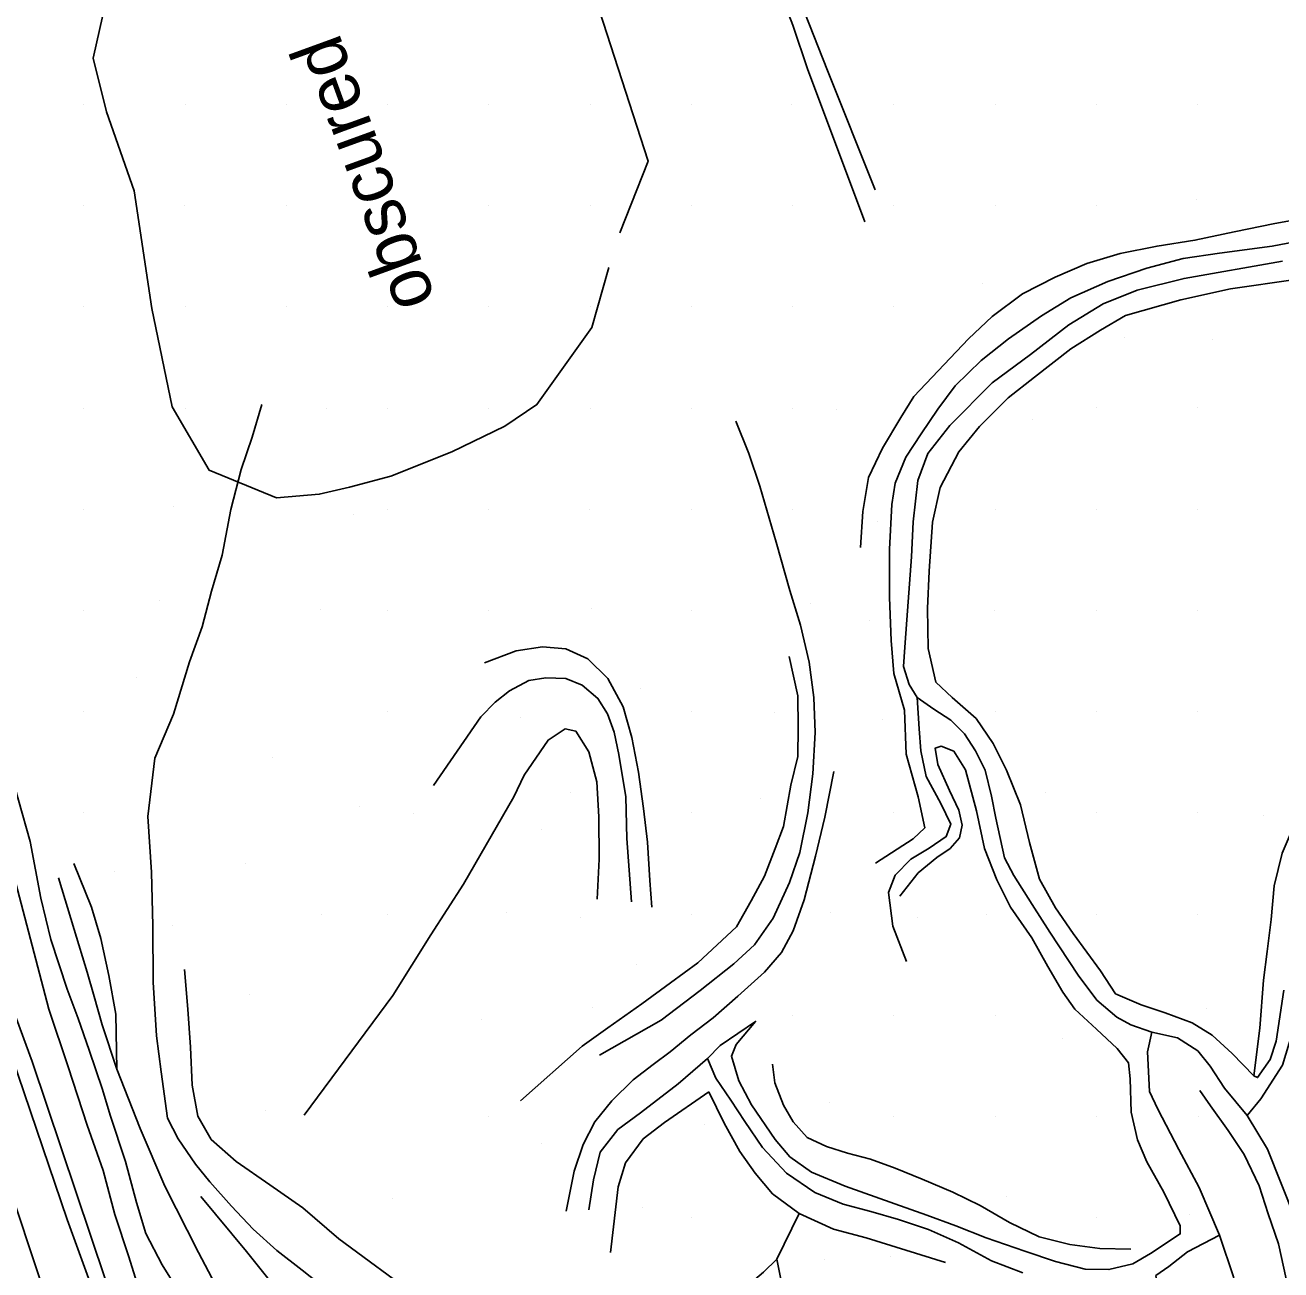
# Model space of a CAD drawing. Extents: x 524772 to 528246, y 273285 to 283088.
# Drawn here: x 527528.2 to 527649.1, y 275047 to 275166.9 of the extents above; entities that cross this region are included whole.
import ezdxf

# ---------------------------------------------------------------- set-up
doc = ezdxf.new("R2010")
doc.units = 0
for name, color, linetype in [('Exist Roads EOP', 7, 'Continuous'), ('Old_Level_12', 7, 'Continuous'), ('PH Exist DTM Breakline', 7, 'Continuous'), ('PH Exist DTM Point', 7, 'Continuous')]:
    doc.layers.add(name, color=color, linetype=linetype)

msp = doc.modelspace()

# ---------------------------------------------------------------- linework, layer by layer
at = {"layer": 'Exist Roads EOP'}
msp.add_lwpolyline([(527557.33, 274967.92), (527554.23, 274976.84), (527550.98, 274985.92), (527547.88, 274994.5), (527544.63, 275003.37), (527541.61, 275011.89), (527538.76, 275019.97), (527535.6, 275028.88), (527532.53, 275037.58), (527529.54, 275046.21), (527526.67, 275054.92), (527523.59, 275063.95), (527520.5, 275073.17), (527517.44, 275081.95), (527514.42, 275090.92), (527511.41, 275100.07), (527508.35, 275109.17), (527505.31, 275118.01), (527502.3, 275127.13), (527499.34, 275135.95), (527496.45, 275144.85), (527493.43, 275153.77), (527490.39, 275163.02), (527487.41, 275171.98)], dxfattribs=at)
at = {"layer": 'Old_Level_12'}
for points in [[(527571.94, 275204.06), (527588.18, 275153.81), (527585.46, 275146.92)], [(527584.39, 275143.58), (527582.76, 275137.81), (527577.46, 275130.37), (527574.37, 275128.3), (527569.27, 275125.83), (527563.4, 275123.48), (527559.41, 275122.4), (527556.49, 275121.73), (527552.37, 275121.37), (527545.89, 275124.06), (527542.33, 275130.14), (527540.37, 275139.63), (527538.68, 275150.97), (527536, 275158.58), (527534.72, 275163.75), (527536.23, 275170.5)]]:
    msp.add_lwpolyline(points, dxfattribs=at)
at = {"layer": 'PH Exist DTM Breakline'}
for points in [[(527541.6, 275027.7), (527539.52, 275031.85), (527537.7, 275036.61), (527535.69, 275042.3), (527532.21, 275051.86), (527525.09, 275072.77), (527519.34, 275088.9), (527512.08, 275109.52), (527505.54, 275127.78), (527498.74, 275147.86), (527489.52, 275175.73), (527483.81, 275193.24), (527479.27, 275206.95), (527472.68, 275226.01)], [(527476.76, 275224.02), (527481.8, 275209.27), (527488.68, 275188.15), (527499.67, 275152.86), (527507.56, 275128.39), (527513.7, 275110.47), (527522.56, 275084.11), (527528.85, 275067.08), (527537.33, 275041.84)], [(527609.05, 275147.98), (527605.95, 275156.31), (527603.57, 275162.63), (527602.11, 275166.92), (527599.84, 275172.85), (527596.76, 275180.06), (527592.79, 275189.7), (527588.85, 275200.37)], [(527591.49, 275197.45), (527596.71, 275183.97), (527601.93, 275171.54), (527605.46, 275162.56), (527610.05, 275151.06)], [(527673.24, 275151.19), (527670.84, 275150.91), (527667.76, 275150.79), (527664.86, 275150.42), (527662.1, 275149.82), (527659.3, 275149.16), (527656.16, 275148.96), (527652.48, 275148.53), (527648.57, 275147.81), (527644.65, 275147), (527640.85, 275146.2), (527637.21, 275145.64), (527633.66, 275144.94), (527630.44, 275143.97), (527627.4, 275142.66), (527624.25, 275141.04), (527621.31, 275138.87), (527619.06, 275136.71), (527613.77, 275131.15), (527612.54, 275129.14), (527610.75, 275126.18), (527609.41, 275123.35), (527608.87, 275120.08), (527608.63, 275116.61)], [(527612.87, 275100.94), (527611.86, 275104.46), (527611.59, 275107.64), (527611.45, 275111.79), (527611.45, 275116.43), (527611.65, 275120.74), (527611.97, 275122.79), (527613, 275125.31), (527614.49, 275127.55), (527616.08, 275129.92), (527617.75, 275132.18), (527620.26, 275134.63), (527622.89, 275136.72), (527626.08, 275138.92), (527628.9, 275140.65), (527632.47, 275142.23), (527636.22, 275143.5), (527639.73, 275144.44), (527643.21, 275144.95), (527648.29, 275145.63), (527651.31, 275146.22)], [(527644.62, 275046.22), (527643.21, 275050.33), (527641.28, 275054.93), (527639.3, 275058.59), (527637.29, 275062.49), (527636.49, 275064.17), (527636.29, 275068), (527636.71, 275069.91), (527634.67, 275070.61), (527633.32, 275071.33), (527631.42, 275072.98), (527629.62, 275075.38), (527626.89, 275079.54), (527625.18, 275082.21), (527623.41, 275084.99), (527622.5, 275086.7), (527621.69, 275090.51), (527621.27, 275092.65), (527620.64, 275095.14), (527619.71, 275097.01), (527618.67, 275098.66), (527617.33, 275099.96), (527615.69, 275101.03), (527614.11, 275102.15), (527613.32, 275103.4), (527612.77, 275105.14), (527612.9, 275106.98), (527613.1, 275109.63), (527613.56, 275115.7), (527613.72, 275119.07), (527614.15, 275123.04), (527615.14, 275125.67), (527617.24, 275128.35), (527621.31, 275132.47), (527625.01, 275135.18), (527628.72, 275138.04), (527632.02, 275140.07), (527635.3, 275141.38), (527639.82, 275142.53), (527649.31, 275144.18)], [(527633.2, 275073.58), (527631.75, 275075.8), (527629.14, 275079.4), (527627.42, 275081.88), (527625.89, 275084.65), (527624.92, 275088.16), (527624.05, 275091.8), (527622.72, 275095.14), (527621.42, 275097.71), (527619.79, 275100.11), (527617.46, 275102.13), (527615.91, 275103.61), (527615.17, 275106.88), (527615.11, 275110.73), (527615.25, 275114.33), (527615.57, 275119.03), (527616.31, 275122.38), (527618.1, 275125.81), (527620.12, 275128.26), (527622.88, 275131.03), (527625.39, 275133), (527628.89, 275135.74), (527631.75, 275137.53), (527634.18, 275138.94), (527639.5, 275140.46), (527644.28, 275141.52), (527650.54, 275142.41)], [(527540.67, 275096.29), (527542.45, 275100.55), (527544.01, 275105.57), (527545.23, 275108.97), (527546.11, 275112.4), (527547.14, 275115.86), (527547.98, 275120.27), (527548.97, 275124.1), (527550.03, 275127.22), (527550.95, 275130.37)], [(527583.48, 275067.69), (527589.43, 275071.06), (527593.2, 275073.92), (527596.43, 275076.48), (527598.42, 275078.32), (527600.23, 275080.88), (527601.8, 275084.33), (527602.79, 275087.22), (527603.57, 275091.03), (527604.05, 275094.79), (527604.26, 275098.76), (527604.13, 275102.16), (527603.7, 275105.56), (527602.86, 275109.1), (527601.83, 275112.45), (527600.52, 275117.12), (527598.95, 275122.51), (527597.87, 275125.66), (527596.62, 275128.78)], [(527572.41, 275105.49), (527575.46, 275106.64), (527577.99, 275107.04), (527580.25, 275106.82), (527582.36, 275105.86), (527584.31, 275103.97), (527585.79, 275101.26), (527586.61, 275098.28), (527587.25, 275094.94), (527587.73, 275091.45), (527588.12, 275088.21), (527588.33, 275084.52), (527588.54, 275081.94)], [(527575.88, 275063.28), (527581.81, 275068.55), (527584.31, 275070.33), (527587.57, 275072.64), (527590.32, 275074.66), (527592.98, 275076.59), (527596.69, 275080.04), (527598.12, 275082.55), (527599.4, 275084.94), (527600.41, 275087.59), (527601.21, 275089.73), (527601.94, 275093.71), (527602.6, 275096.47), (527602.64, 275099.25), (527602.59, 275102.29), (527601.78, 275106.08)], [(527646.52, 275065.68), (527647.11, 275070.27), (527647.47, 275074.91), (527647.82, 275077.66), (527648.21, 275080.75), (527648.49, 275084), (527649.26, 275087.13), (527650.23, 275089.39), (527651.82, 275091.5), (527654.07, 275093.35), (527656.96, 275094.9), (527660.25, 275096.2), (527664.03, 275097.51), (527667.55, 275098.63), (527670.95, 275100.17), (527673.73, 275101.9), (527678.5, 275104.97), (527681.8, 275106.88)], [(527586.57, 275082.45), (527586.12, 275088.55), (527586.04, 275092.58), (527585.35, 275096.65), (527584.92, 275098.79), (527584.28, 275100.56), (527583.34, 275102.05), (527581.81, 275103.34), (527580.24, 275103.99), (527578.34, 275104.05), (527576.69, 275103.78), (527574.82, 275102.79), (527573.43, 275101.69), (527572.07, 275100.28), (527567.5, 275093.67)], [(527636.71, 275069.91), (527639.17, 275069.36), (527641.14, 275068.09), (527642.34, 275066.61), (527643.72, 275064.51), (527645.9, 275061.86), (527647.22, 275063.46), (527649.29, 275066.73), (527651, 275072.35), (527651.39, 275075.82), (527651.56, 275078.96), (527651.93, 275082.02), (527652.32, 275084.21), (527653.09, 275086.84), (527654.18, 275088.74), (527657.78, 275090.8), (527661.55, 275092.34), (527665.8, 275093.99), (527668.68, 275095.21), (527672.11, 275096.96), (527675.89, 275098.78), (527680.74, 275101.47), (527683.02, 275102.92), (527685.25, 275104.5)], [(527614.11, 275102.15), (527614.29, 275099.13), (527614.46, 275097), (527614.97, 275094.54), (527616.39, 275091.94), (527617.33, 275089.95), (527616.89, 275088.75), (527615.25, 275087.64), (527613.48, 275086.58), (527611.98, 275085.01), (527611.33, 275083.37), (527611.75, 275080.11), (527613.06, 275076.71)], [(527610.08, 275086.17), (527613.71, 275088.54), (527614.83, 275089.58), (527614.18, 275092.56), (527613.03, 275096.67), (527612.87, 275100.94)], [(527583.28, 275082.7), (527583.46, 275086.56), (527583.42, 275090.66), (527583.24, 275094.03), (527582.47, 275096.9), (527581.22, 275098.9), (527580.2, 275099.11), (527578.54, 275098.04), (527576.25, 275094.67), (527575.23, 275092.58), (527570.39, 275084.16), (527567.24, 275079.28), (527563.58, 275073.42), (527555.04, 275061.91)], [(527612.42, 275083), (527614.2, 275085.24), (527616, 275086.74), (527617.27, 275087.58), (527618.17, 275088.61), (527618.42, 275089.84), (527618.11, 275091.28), (527617.23, 275093.19), (527616.08, 275095.7), (527615.83, 275097.26), (527616.41, 275097.45), (527617.63, 275096.96), (527618.76, 275095.17), (527619.8, 275091.22), (527620.59, 275087.58), (527621.76, 275084.56), (527623.09, 275081.95), (527625.14, 275079), (527626.68, 275076.23), (527628.13, 275073.74), (527629.29, 275072.12), (527631.38, 275070.18), (527633.38, 275068.33), (527634.47, 275066.94), (527634.63, 275065.4), (527634.7, 275062.2), (527635.33, 275059.52), (527636.21, 275057.41), (527637.87, 275054.47), (527639.43, 275051.25)], [(527543.49, 275044.08), (527541.36, 275047.49), (527539.78, 275050.5), (527538.89, 275053.5), (527537.84, 275057.43), (527536.36, 275061.89), (527535.6, 275064.38), (527534.33, 275068.16), (527533.28, 275071.2), (527532.22, 275074.04), (527530.65, 275078.82), (527529.69, 275082.8), (527528.64, 275088.26), (527526.4, 275096.22)], [(527541.88, 275061.6), (527541.28, 275066.09), (527540.81, 275069.54), (527540.49, 275074.72), (527540.45, 275080.14), (527540.35, 275085.3), (527539.97, 275090.69), (527540.67, 275096.29)], [(527580.3, 275052.64), (527581.06, 275056.49), (527581.92, 275059.08), (527583.04, 275061.25), (527584.68, 275063.27), (527586.74, 275065.29), (527588.67, 275066.77), (527590.29, 275068.01), (527592.31, 275069.63), (527594.44, 275071.27), (527596.82, 275073.38), (527599.39, 275075.69), (527601.04, 275077.57), (527602.15, 275079.66), (527603.22, 275082.64), (527604.3, 275086.86), (527605.2, 275090.6), (527606.08, 275095.01)], [(527526.03, 275089.03), (527530.44, 275072.1), (527532.32, 275066.56), (527534.13, 275060.94), (527535.68, 275056.58), (527536.79, 275052.32), (527538.15, 275048.24), (527539.08, 275045.25)], [(527531.39, 275084.78), (527532.9, 275079.8), (527534.15, 275075.68), (527534.81, 275073.33), (527535.59, 275070.6), (527537.01, 275066.33), (527536.9, 275071.63), (527536.24, 275075.35), (527535.47, 275078.91), (527534.57, 275081.95), (527532.87, 275086.16)], [(527566.07, 275044.32), (527558.37, 275049.99), (527554.9, 275052.98), (527551.75, 275055.2), (527548.5, 275057.44), (527546.09, 275059.57), (527544.81, 275061.81), (527544.24, 275064.79), (527544.1, 275068.44), (527543.83, 275072.11), (527543.52, 275075.93)], [(527649.43, 275073.93), (527648.69, 275069.03), (527648.1, 275067.26), (527646.89, 275065.52), (527646.52, 275065.68), (527644.43, 275067.83), (527642.51, 275069.61), (527640.6, 275070.81), (527637.98, 275071.76), (527635.69, 275072.52), (527633.2, 275073.58)], [(527624.29, 275046.7), (527621.27, 275047.86), (527618.07, 275049.6), (527615.18, 275050.88), (527612.3, 275051.84), (527609.63, 275052.62), (527606.96, 275053.33), (527604.24, 275054.44), (527601.5, 275056.31), (527599.21, 275058.79), (527597.51, 275061.29), (527596.16, 275063.36), (527594.7, 275065.46), (527593.91, 275067.35), (527595.13, 275068.62), (527598.54, 275070.93), (527596.67, 275068.7), (527596.21, 275067.57), (527596.91, 275065.21), (527598.15, 275062.88), (527600.43, 275059.57), (527601.82, 275057.89), (527603.92, 275056.4), (527607.17, 275055.06), (527611.94, 275053.35), (527615.04, 275052.27), (527617.81, 275051.23), (527620.76, 275050.09), (527624.47, 275048.81), (527627.43, 275047.79), (527630.29, 275047.05), (527632.58, 275047.02), (527634.87, 275047.58), (527636.58, 275048.56), (527639.45, 275050.45), (527639.43, 275051.25)], [(527582.46, 275052.78), (527582.91, 275055.66), (527583.56, 275058.35), (527585.27, 275060.53), (527587.45, 275062.12), (527591.08, 275064.92), (527593.91, 275067.35)], [(527550.32, 275038.29), (527544.88, 275048.66), (527541.63, 275055.05), (527539.25, 275060.61), (527537.01, 275066.33)], [(527634.67, 275049), (527631.7, 275049.06), (527628.8, 275049.44), (527625.84, 275050.17), (527623, 275051.55), (527620.16, 275053.2), (527617.55, 275054.48), (527614.59, 275055.72), (527611.98, 275056.79), (527609.61, 275057.66), (527607.38, 275058.25), (527605.37, 275058.87), (527603.51, 275059.74), (527602.14, 275061.26), (527601.22, 275062.87), (527600.38, 275065), (527600.17, 275066.8)], [(527594.03, 275064.15), (527589.76, 275061.2), (527587.69, 275059.61), (527586, 275057.3), (527585.28, 275055), (527584.54, 275048.68)], [(527594.03, 275064.15), (527595.52, 275061.12), (527597.01, 275058.41), (527598.5, 275056.3), (527600.15, 275054.33), (527602.73, 275052.43), (527606.04, 275050.92), (527609.2, 275050.07), (527613, 275048.89), (527616.82, 275047.71)], [(527665.78, 275027.66), (527662.79, 275025.74), (527659.42, 275024.93), (527656.9, 275024.55), (527655.05, 275024.42), (527653.63, 275025.09), (527652.68, 275027.89), (527651.73, 275032.09), (527650.4, 275036.84), (527649.97, 275040.38), (527649.96, 275043.45), (527649.65, 275046.13), (527648.9, 275049.49), (527647.92, 275052.39), (527647.06, 275055.09), (527645.61, 275058.11), (527644.07, 275060.41), (527642.35, 275062.79), (527641.33, 275064.28)], [(527586.61, 275018.62), (527582.97, 275022.35), (527559.3, 275043.43), (527554.86, 275046.98), (527552.41, 275048.86), (527550.12, 275050.93), (527548.05, 275053.13), (527545.96, 275055.46), (527544.58, 275057.18), (527542.89, 275059.61), (527541.88, 275061.6)], [(527645.9, 275061.86), (527647.85, 275058.63), (527650.47, 275052.02), (527651.95, 275047.69)], [(527555.56, 275041.17), (527549.49, 275048.76), (527545.08, 275054.07)], [(527600.57, 275048.01), (527602.73, 275052.43)], [(527643.21, 275050.33), (527640.13, 275048.73), (527638.36, 275047.32), (527637.1, 275046.45), (527637.97, 275040.7), (527638.62, 275036.85), (527638.78, 275034.11), (527638.82, 275030.31), (527638.85, 275026.76), (527638.86, 275024.69), (527638.66, 275021.43), (527638.37, 275018.89), (527639.36, 275014.69)], [(527604.3, 275036.49), (527601.9, 275042.82), (527601.13, 275045.3), (527600.57, 275048.01), (527599.3, 275046.77), (527597.4, 275045.16), (527596.14, 275043.94)]]:
    msp.add_lwpolyline(points, dxfattribs=at)
at = {"layer": 'PH Exist DTM Point'}
for p, q in [((527533.82, 275159.29), (527533.82, 275159.29)), ((527543.58, 275159.29), (527543.58, 275159.29)), ((527553.33, 275159.29), (527553.33, 275159.29)), ((527563.09, 275159.29), (527563.09, 275159.29)), ((527572.84, 275159.29), (527572.84, 275159.29)), ((527582.59, 275159.29), (527582.59, 275159.29)), ((527592.35, 275159.29), (527592.35, 275159.29)), ((527601.95, 275159.31), (527601.95, 275159.31)), ((527611.85, 275159.29), (527611.85, 275159.29)), ((527621.61, 275159.29), (527621.61, 275159.29)), ((527631.39, 275159.28), (527631.39, 275159.28)), ((527641.11, 275159.29), (527641.11, 275159.29)), ((527533.82, 275149.54), (527533.82, 275149.54)), ((527543.55, 275149.55), (527543.55, 275149.55)), ((527553.33, 275149.54), (527553.33, 275149.54)), ((527563.09, 275149.54), (527563.09, 275149.54)), ((527572.84, 275149.54), (527572.84, 275149.54)), ((527582.59, 275149.54), (527582.59, 275149.54)), ((527592.35, 275149.54), (527592.35, 275149.54)), ((527602.1, 275149.54), (527602.1, 275149.54)), ((527611.85, 275149.54), (527611.85, 275149.54)), ((527621.61, 275149.54), (527621.61, 275149.54)), ((527631.36, 275149.54), (527631.36, 275149.54)), ((527641.04, 275150.14), (527641.04, 275150.14)), ((527620.37, 275142.05), (527620.37, 275142.05)), ((527533.82, 275139.79), (527533.82, 275139.79)), ((527543.58, 275139.79), (527543.58, 275139.79)), ((527553.33, 275139.79), (527553.33, 275139.79)), ((527563.09, 275139.79), (527563.09, 275139.79)), ((527572.84, 275139.79), (527572.84, 275139.79)), ((527582.59, 275139.79), (527582.59, 275139.79)), ((527592.35, 275139.79), (527592.35, 275139.79)), ((527602.1, 275139.79), (527602.1, 275139.79)), ((527611.79, 275139.79), (527611.79, 275139.79)), ((527634.1, 275136.8), (527634.1, 275136.8)), ((527642.58, 275136.66), (527642.58, 275136.66)), ((527533.82, 275130.03), (527533.82, 275130.03)), ((527543.58, 275130.03), (527543.58, 275130.03)), ((527557.19, 275129.97), (527557.19, 275129.97)), ((527563.09, 275130.03), (527563.09, 275130.03)), ((527572.84, 275130.03), (527572.84, 275130.03)), ((527582.59, 275130.03), (527582.59, 275130.03)), ((527592.35, 275130.03), (527592.35, 275130.03)), ((527602.1, 275130.03), (527602.1, 275130.03)), ((527631.34, 275130.05), (527631.34, 275130.05)), ((527641.11, 275130.05), (527641.11, 275130.05)), ((527606.29, 275129.85), (527606.29, 275129.85)), ((527625.23, 275128.93), (527625.23, 275128.93)), ((527542.46, 275120.58), (527542.46, 275120.58)), ((527533.82, 275120.28), (527533.82, 275120.28)), ((527559.78, 275119.77), (527559.78, 275119.77)), ((527563.09, 275120.28), (527563.09, 275120.28)), ((527572.84, 275120.28), (527572.84, 275120.28)), ((527582.58, 275120.26), (527582.58, 275120.26)), ((527592.35, 275120.28), (527592.35, 275120.28)), ((527602.1, 275120.28), (527602.1, 275120.28)), ((527610.28, 275119.08), (527610.28, 275119.08)), ((527621.61, 275120.28), (527621.61, 275120.28)), ((527631.39, 275120.27), (527631.39, 275120.27)), ((527641.11, 275120.28), (527641.11, 275120.28)), ((527541.15, 275111.52), (527541.15, 275111.52)), ((527556.64, 275110.64), (527556.64, 275110.64)), ((527582.76, 275110.68), (527582.76, 275110.68)), ((527603.86, 275111.16), (527603.86, 275111.16)), ((527533.82, 275110.53), (527533.82, 275110.53)), ((527563.07, 275110.52), (527563.07, 275110.52)), ((527572.84, 275110.53), (527572.84, 275110.53)), ((527592.35, 275110.53), (527592.35, 275110.53)), ((527609.5, 275109.6), (527609.5, 275109.6)), ((527621.59, 275110.52), (527621.59, 275110.52)), ((527631.36, 275110.53), (527631.36, 275110.53)), ((527641.11, 275110.53), (527641.11, 275110.53)), ((527538.9, 275104.04), (527538.9, 275104.04)), ((527587.4, 275102.99), (527587.4, 275102.99)), ((527533.82, 275100.77), (527533.82, 275100.77)), ((527563.09, 275100.77), (527563.09, 275100.77)), ((527575.85, 275100.2), (527575.85, 275100.2)), ((527592.35, 275100.77), (527592.35, 275100.77)), ((527600.36, 275100.7), (527600.36, 275100.7)), ((527610.72, 275100.05), (527610.72, 275100.05)), ((527621.61, 275100.77), (527621.61, 275100.77)), ((527631.36, 275100.77), (527631.36, 275100.77)), ((527641.12, 275100.75), (527641.12, 275100.75)), ((527551.95, 275096.41), (527551.95, 275096.41)), ((527580.7, 275093.01), (527580.7, 275093.01)), ((527626.51, 275092.97), (527626.51, 275092.97)), ((527560.38, 275091.69), (527560.38, 275091.69)), ((527598.98, 275092.37), (527598.98, 275092.37)), ((527533.82, 275091.02), (527533.82, 275091.02)), ((527565.58, 275090.96), (527565.58, 275090.96)), ((527592.35, 275091.02), (527592.35, 275091.02)), ((527611.85, 275091.02), (527611.85, 275091.02)), ((527631.36, 275091.02), (527631.36, 275091.02)), ((527641.11, 275091.04), (527641.11, 275091.04)), ((527647.48, 275090.8), (527647.48, 275090.8)), ((527577.89, 275089.4), (527577.89, 275089.4)), ((527536.81, 275085.35), (527536.81, 275085.35)), ((527549.35, 275086.18), (527549.35, 275086.18)), ((527556.67, 275081.22), (527556.67, 275081.22)), ((527563.04, 275081.27), (527563.04, 275081.27)), ((527574.54, 275081.38), (527574.54, 275081.38)), ((527581.7, 275080.99), (527581.7, 275080.99)), ((527592.35, 275081.27), (527592.35, 275081.27)), ((527605.72, 275081.46), (527605.72, 275081.46)), ((527614.09, 275080.9), (527614.09, 275080.9)), ((527620.75, 275081.24), (527620.75, 275081.24)), ((527631.34, 275081.28), (527631.34, 275081.28)), ((527641.11, 275081.27), (527641.11, 275081.27)), ((527542.34, 275080.2), (527542.34, 275080.2)), ((527587.09, 275076.41), (527587.09, 275076.41)), ((527549.82, 275073.53), (527549.82, 275073.53)), ((527582.86, 275072.29), (527582.86, 275072.29)), ((527641.99, 275072.2), (527641.99, 275072.2)), ((527572.08, 275071.13), (527572.08, 275071.13)), ((527602.1, 275071.51), (527602.1, 275071.51)), ((527611.85, 275071.51), (527611.85, 275071.51)), ((527621.61, 275071.51), (527621.61, 275071.51)), ((527628.13, 275069.28), (527628.13, 275069.28)), ((527551.36, 275062.36), (527551.36, 275062.36)), ((527605.66, 275063.08), (527605.66, 275063.08)), ((527572.84, 275061.76), (527572.84, 275061.76)), ((527611.83, 275061.77), (527611.83, 275061.77)), ((527621.61, 275061.76), (527621.61, 275061.76)), ((527631.36, 275061.76), (527631.36, 275061.76)), ((527641.17, 275061.77), (527641.17, 275061.77)), ((527593.65, 275060.96), (527593.65, 275060.96)), ((527577.92, 275059.15), (527577.92, 275059.15)), ((527563.59, 275053.9), (527563.59, 275053.9)), ((527622.67, 275054.05), (527622.67, 275054.05)), ((527587.62, 275053.03), (527587.62, 275053.03)), ((527592.35, 275052), (527592.35, 275052)), ((527631.36, 275052), (527631.36, 275052)), ((527640.38, 275052.33), (527640.38, 275052.33)), ((527605.15, 275047.95), (527605.15, 275047.95)), ((527611.57, 275048.29), (527611.57, 275048.29))]:
    msp.add_line(p, q, dxfattribs=at)

# ---------------------------------------------------------------- texts
at = {"layer": 'Old_Level_12'}
msp.add_text('obscured', height=5, rotation=110, dxfattribs=at).set_placement((527567.75, 275140.47))

doc.saveas('drawing.dxf')
